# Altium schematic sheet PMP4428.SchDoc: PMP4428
size 431 x 279 mm; Date: Not shown in title block; ApprovedBy: Not shown in title block; CheckedBy: Not shown in title block; Author: Not shown in title block; CompanyName: Not shown in title block; Engineer: David Ji; Organization: Not shown in title block; Address1: Not shown in title block; Address2: Not shown in title block; Address3: Not shown in title block; Address4: Not shown in title block; DocumentNumber: 1; Revision: A; SheetNumber: 1; SheetTotal: 2; PageSetup: Record=PageOptions|CenterHorizontal=True|CenterVertical=True|PrintScale=0.66|XCorrection=1.00|YCorrection=1.00|PrintKind=0|BorderSize=5000000|LeftOffset=0|BottomOffset=0|Orientation=2|PaperLength=1000|PaperWidth=1000|Scale=100|PaperSource=15|PrintQuality=600|MediaType=1|DitherType=10|PaperKind=Custom...|PrintScaleMode=1
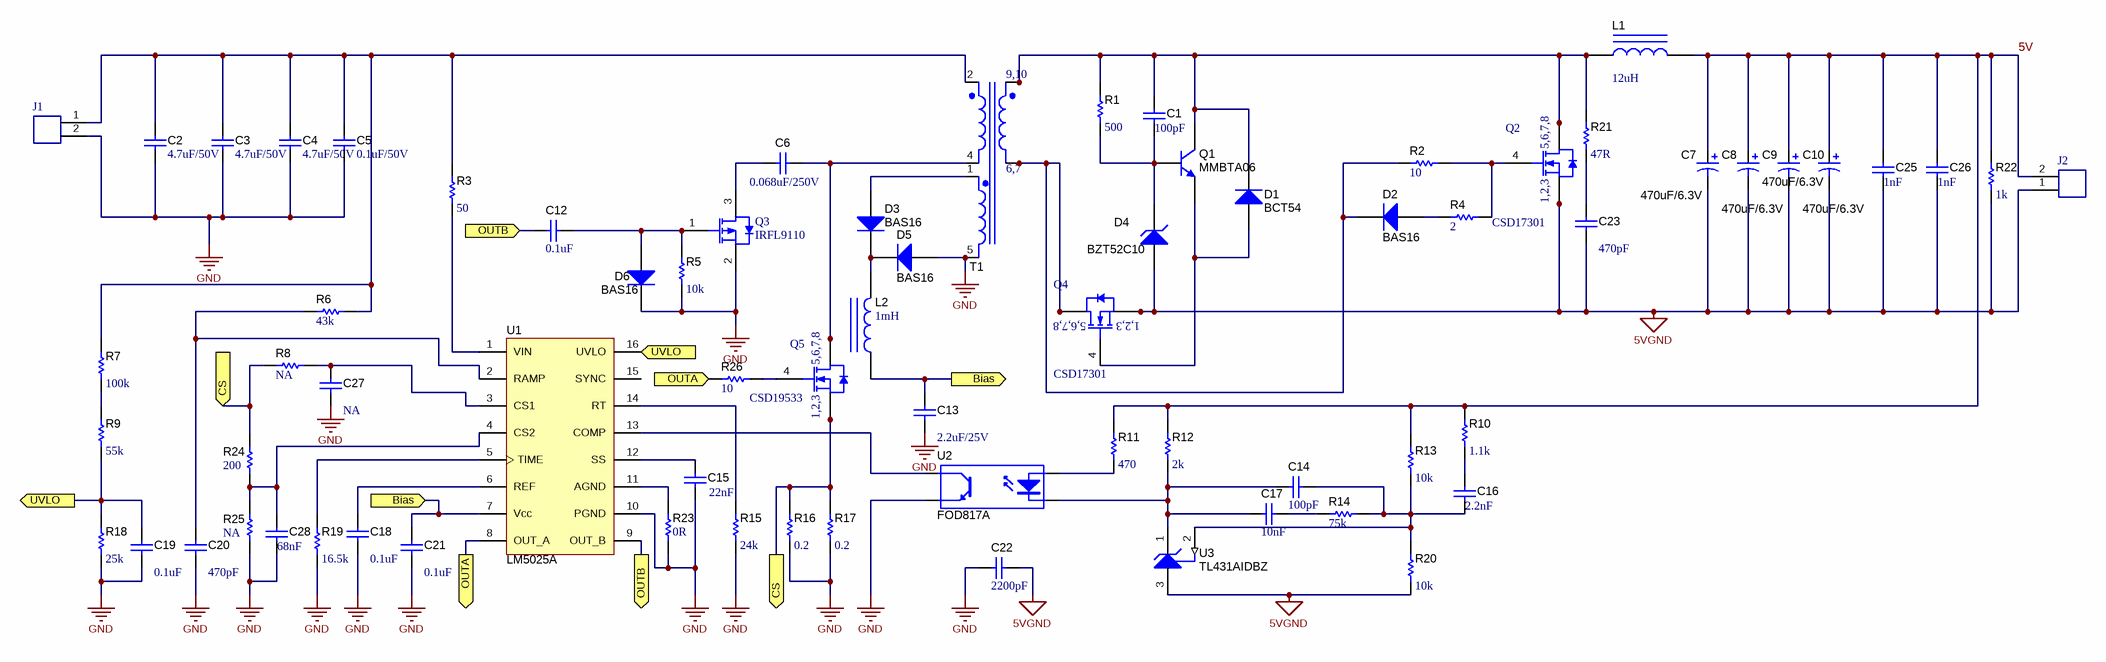
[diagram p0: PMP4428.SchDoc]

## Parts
C1  value 100pF  [0603]  (hidden comment: Cap)
C2  value 4.7uF/50V  [1206]  (hidden comment: Cap)
C3  value 4.7uF/50V  [1206]  (hidden comment: Cap)
C4  value 4.7uF/50V  [1206]  (hidden comment: Cap)
C5  value 0.1uF/50V  [0805]  (hidden comment: Cap)
C6  value 0.068uF/250V  [1206]  (hidden comment: Cap)
C7  470uF/6.3V  [POSCAP B2E size]
C8  470uF/6.3V  [POSCAP B2E size]
C9  470uF/6.3V  [POSCAP B2E size]
C10  470uF/6.3V  [POSCAP B2E size]
C12  value 0.1uF  [0603]  (hidden comment: Cap)
C13  value 2.2uF/25V  [0805]  (hidden comment: Cap)
C14  value 100pF  [0603]  (hidden comment: Cap)
C15  value 22nF  [0603]  (hidden comment: Cap)
C16  value 2.2nF  [0603]  (hidden comment: Cap)
C17  value 10nF  [0603]  (hidden comment: Cap)
C18  value 0.1uF  [0603]  (hidden comment: Cap)
C19  value 0.1uF  [0603]  (hidden comment: Cap)
C20  value 470pF  [0603]  (hidden comment: Cap)
C21  value 0.1uF  [0603]  (hidden comment: Cap)
C22  value 2200pF  [1812_HV]  (hidden comment: Cap)
C23  value 470pF  [0805]  (hidden comment: Cap)
C25  value 1nF  [0603]  (hidden comment: Cap)
C26  value 1nF  [0603]  (hidden comment: Cap)
C27  value NA  [0603]  (hidden comment: Cap)
C28  value 68nF  [0603]  (hidden comment: Cap)
D1  BCT54  [SOT-23_N]
D2  BAS16  [SOT-23_N]
D3  BAS16  [SOT-23_N]
D4  BZT52C10  [SOD-123]
D5  BAS16  [SOT-23_N]
D6  BAS16  [SOT-23_N]
J1  (no value)  [Connector]
J2  (no value)  [J2 Connector]
L1  value 12uH  [L1]  (hidden comment: 7443551111)
L2  value 1mH  [L2]  (hidden comment: LPS4414)
Q1  MMBTA06  [SOT-23]
Q2  CSD17301  [PG-TDSON-8]
Q3  IRFL9110  [SOT223_L]
Q4  CSD17301  [PG-TDSON-8]
Q5  CSD19533  [PG-TDSON-8]
R1  value 500  [0603]  (hidden comment: Res1)
R2  value 10  [0603]  (hidden comment: Res1)
R3  value 50  [1206]  (hidden comment: Res1)
R4  value 2  [0603]  (hidden comment: Res1)
R5  value 10k  [0805]  (hidden comment: Res1)
R6  value 43k  [0603]  (hidden comment: Res1)
R7  value 100k  [0603]  (hidden comment: Res1)
R8  value NA  [0603]  (hidden comment: Res1)
R9  value 55k  [0603]  (hidden comment: Res1)
R10  value 1.1k  [0603]  (hidden comment: Res1)
R11  value 470  [0603]  (hidden comment: Res1)
R12  value 2k  [0603]  (hidden comment: Res1)
R13  value 10k  [0603]  (hidden comment: Res1)
R14  value 75k  [0603]  (hidden comment: Res1)
R15  value 24k  [0603]  (hidden comment: Res1)
R16  value 0.2  [1812M]  (hidden comment: Res1)
R17  value 0.2  [1812M]  (hidden comment: Res1)
R18  value 25k  [0603]  (hidden comment: Res1)
R19  value 16.5k  [0603]  (hidden comment: Res1)
R20  value 10k  [0603]  (hidden comment: Res1)
R21  value 47R  [1206]  (hidden comment: Res1)
R22  value 1k  [1206]  (hidden comment: Res1)
R23  value 0R  [0603]  (hidden comment: Res1)
R24  value 200  [0603]  (hidden comment: Res1)
R25  value NA  [0603]  (hidden comment: Res1)
R26  value 10  [0603]  (hidden comment: Res1)
T1  ACF Transformer  [WURTH_750313995]  (value not drawn)
U1  LM5025A  [PW0016A_L]
U2  FOD817A  [N04C]
U3  TL431AIDBZ  [SOT-23_N]

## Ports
Bias (in), Bias (out), CS (in), CS (out), OUTA (in), OUTA (out), OUTB (in), OUTB (out), UVLO (in), UVLO (out)

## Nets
5VGND: C7.2 C8.2 C9.2 C10.2 C22.1 C23.1 C25.1 C26.1 D4.1(A) J2.1(Vin+) Q2.1(S) Q2.2(S) Q2.3(S) Q4.1(S) Q4.2(S) Q4.3(S) R20.1 R22.1 U3.3(ANODE)
GND: C2.2 C3.2 C4.2 C5.2 C13.1 C15.1 C18.1 C19.1 C20.1 C21.1 C22.2 C27.1 C28.1 D5.1(A) D6.3(K) J1.2(Vin-) Q3.2(S) R5.1 R15.1 R16.1 R17.1 R18.1 R19.1 R23.2 R25.2 T1.5(Aux-) U1.10(PGND) U2.3(E)
5V: C7.1 C8.1 C9.1 C10.1 C25.2 C26.2 J2.2(Vin-) L1.2 R10.2 R11.2 R12.2 R13.2 R22.2
Bias: C13.2 C21.2 L2.1 U1.7(Vcc) ; port Bias
CS: Q5.1(S) Q5.2(S) Q5.3(S) R8.2 R16.2 R17.2 R24.1 ; port CS
OUTA: R26.2 U1.8(OUT_A) ; port OUTA
OUTB: C12.2 U1.9(OUT_B) ; port OUTB
UVLO: C19.2 R9.1 R18.2 U1.16(UVLO) ; port UVLO
NetC1_1: C1.1 D4.2(K) Q1.2(B) R1.1
NetC1_2: C1.2 D1.3(K) L1.1 Q1.3(C) Q2.5(D) Q2.6(D) Q2.7(D) Q2.8(D) Q2.9(D) R1.2 R21.2 T1.9(Sec+) T1.10(Sec+)
NetC2_1: C2.1 C3.1 C4.1 C5.1 J1.1(Vin+) R3.2 R6.1 R7.2 T1.2(Pri+)
NetC6_1: C6.1 Q5.5(D) Q5.6(D) Q5.7(D) Q5.8(D) Q5.9(D) T1.4(Pri_)
NetC6_2: C6.2 Q3.3(D)
NetC12_1: C12.1 D6.1(A) Q3.1(G) R5.2
NetC14_1: C14.1 C16.1 R13.1 R14.1 R20.2 U3.2(REF)
NetC14_2: C14.2 C17.2 R12.1 U2.2(K) U3.1(CATHODE)
NetC15_2: C15.2 U1.12(SS)
NetC16_2: C16.2 R10.1
NetC17_1: C17.1 R14.2
NetC18_2: C18.2 U1.6(REF)
NetC20_2: C20.2 R6.2 U1.2(RAMP)
NetC23_2: C23.2 R21.1
NetC27_2: C27.2 R8.1 U1.3(CS1)
NetC28_2: C28.2 R24.2 R25.1 U1.4(CS2)
NetD1_1: D1.1(A) Q1.1(E) Q4.4(G)
NetD2_1: D2.1(A) R4.2
NetD2_3: D2.3(K) Q4.5(D) Q4.6(D) Q4.7(D) Q4.8(D) Q4.9(D) R2.2 T1.6(Sec-) T1.7(Sec-)
NetD3_1: D3.1(A) T1.1(Aux+)
NetD3_3: D3.3(K) D5.3(K) L2.2
NetQ2_4: Q2.4(G) R2.1 R4.1
NetQ5_4: Q5.4(G) R26.1
NetR3_1: R3.1 U1.1(VIN)
NetR7_1: R7.1 R9.2
NetR11_1: R11.1 U2.1(A)
NetR15_2: R15.2 U1.14(RT)
NetR19_2: R19.2 U1.5(TIME)
NetR23_1: R23.1 U1.11(AGND)
NetU1_13: U1.13(COMP) U2.4(C)

Not connected (* = marked no-connect by the designer): U1 15(SYNC)

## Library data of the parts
C1-C6 C12-C23 C25-C28 = Cap: Capacitor
C7-C10 = Cap Pol1: Polarized Capacitor (Radial)
D1-D3 D5 D6 = Diode: Default Diode
D4 = D Zener: Zener Diode
J1 J2 = Connector
L1 = Inductor Iron: L*W*H 13mm*12.8*6.2mm
L2 = Inductor Iron: L*W*H 4.7mm*4.7*1.4mm
Q1 = 2N3904: NPN General Purpose Amplifier
Q2 Q4 Q5 = CSD19533: NPN MOSFET
Q3 = PMOSFET: PNP MOSFET
R1-R26 = Res1: Resistor
T1 = ACF Transformer: EFD15(TP5); Manufacturer: Used in BOM report; SymbolVersion: use current date i.e. 2008-05-20; SymbolCreator: Use a-id; CompType: Used in some BOM reports.  Useful for finding later.; U/M: EA, IN, or GM
U1 = LM5025A: Active Clamp Voltage Mode PWM Controller; Manufacturer: Used in BOM report; SymbolVersion: use current date i.e. 2008-05-20; SymbolCreator: Use a-id; CompType: Used in some BOM reports.  Useful for finding later.; U/M: EA, IN, or GM
U2 = Optoisolator1: 4-Pin Phototransistor Optocoupler
U3 = TL431AIDBZ: PRECISION PROGRAMMABLE REFERENCE, DBZ0003A; Alternate Manufacturer: None; Manufacturer: Texas Instruments; SymbolCreator: a0412235; CompType: IC; U/M: EA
